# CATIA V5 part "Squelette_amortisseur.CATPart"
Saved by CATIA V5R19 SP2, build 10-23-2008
Part number: squelette_amortisseur
Bounding box of the stored display mesh (mm): x -20 to 20, y -671 to -631, z 125 to 475
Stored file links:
  C:\Users\Pauline\Desktop\CFAO_Catia\Compte_rendu\pmayet_assemblage_animation4\Squelette_amortisseur.CATPart
  C:\Users\Pauline\Desktop\CFAO_Catia\Compte_rendu\pmayet_assemblage_animation4\pmayet_assemblage_animation.CATProduct
  C:\Users\Pauline\Desktop\CFAO_Catia\Compte_rendu\pmayet_assemblage_animation4\Squelette_de_base.CATPart
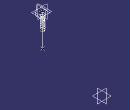
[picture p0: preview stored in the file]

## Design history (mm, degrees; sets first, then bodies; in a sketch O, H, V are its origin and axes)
Set1
  Point1 "Point.19_amortisseur": linked copy from another document
  Point2 "Point.20_amortisseur": linked copy from another document
  Plane1: linked copy from another document
  Plane2: linked copy from another document
  Point3 "Point.21_début_ressort": linked copy from another document
Set2
  Line1: type PtPt, FirstPoint Point1, SecondPoint Point2
  Plane3: type Normal, Curve Line1, RefPoint Point2
  Plane4: type OffsetPt, RefPlane Plane1, RefPoint Point2
  Plane5: type OffsetPt, RefPlane Plane2, RefPoint Point2
  Plane6: type Normal, Curve Line1, RefPoint Point3
  Helix1: Direction Line1, RefPoint Point3, Pitch 20, Height 160, TaperAngle 0
  Plane7: type Normal, Curve Helix1, RefPoint Point3
Body1 (main body)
